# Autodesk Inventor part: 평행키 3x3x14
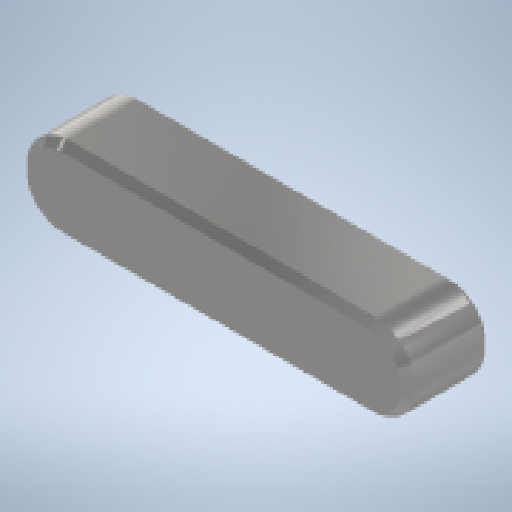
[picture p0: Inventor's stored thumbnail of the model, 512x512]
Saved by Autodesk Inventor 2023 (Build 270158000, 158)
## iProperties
Created: 2024-09
Part Number: 평행키 3x3x14
Material: 강철, 연강
Description: 키 및 해당 키홈
Document SubType Name: Modeling
Designer: home
Density: 7.85 g/cm^3
Appearance: 기본값
Author: jhkim
Sending System: Autodesk Inventor 2025
Preprocessor: ST-DEVELOPER v20
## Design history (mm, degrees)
node "평행키 3x3x141"
node "솔리드1"
body "Solid1"
